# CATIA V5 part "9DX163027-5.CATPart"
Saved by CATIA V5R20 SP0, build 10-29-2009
Part number: 9DX163027-5
Revision: ANY
Definition: UNKNOWN
Nomenclature: 9DX163027-5
Source: Unknown
Bounding box of the stored display mesh (mm): x 0 to 142, y -12 to 12, z -12 to 12
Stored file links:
  C:\Users\Utente\Desktop\IO LAVORO\3D X SITO CF\CUMSA\3D files DX\DX 163027\9DX163027-5.CATPart
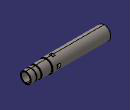
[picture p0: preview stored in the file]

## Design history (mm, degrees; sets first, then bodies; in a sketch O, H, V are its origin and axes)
Body1 "MatrizC1" (main body)
  Solid1: solid without history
